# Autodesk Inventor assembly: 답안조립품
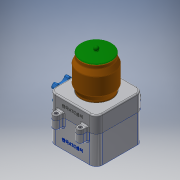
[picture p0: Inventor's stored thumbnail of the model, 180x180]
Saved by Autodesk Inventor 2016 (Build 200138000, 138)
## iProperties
Created: 2018-01
Part Number: 답안조립품
Material: 일반
Document SubType Name: Assembly
Designer: USER
Author: USER
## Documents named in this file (9)
- C:\Users\USER\Desktop\480108V1019\답안조립품.iam
- C:\Users\USER\Desktop\480108V1019\본체.ipt
- C:\Users\USER\Desktop\480108V1019\본체커버.ipt
- C:\Users\USER\Desktop\480108V1019\볼트 M3x12.ipt
- C:\Users\USER\Desktop\480108V1019\볼트 M4x12.ipt
- C:\Users\USER\Desktop\480108V1019\용기.ipt
- C:\Users\USER\Desktop\480108V1019\용기캡.ipt
- C:\Users\USER\Desktop\480108V1019\핸들.ipt
- C:\Users\USER\Desktop\480108V1019\핸들축.ipt
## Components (2 placed, 2 different names)
1. 핸들:1
2. 핸들축:1
